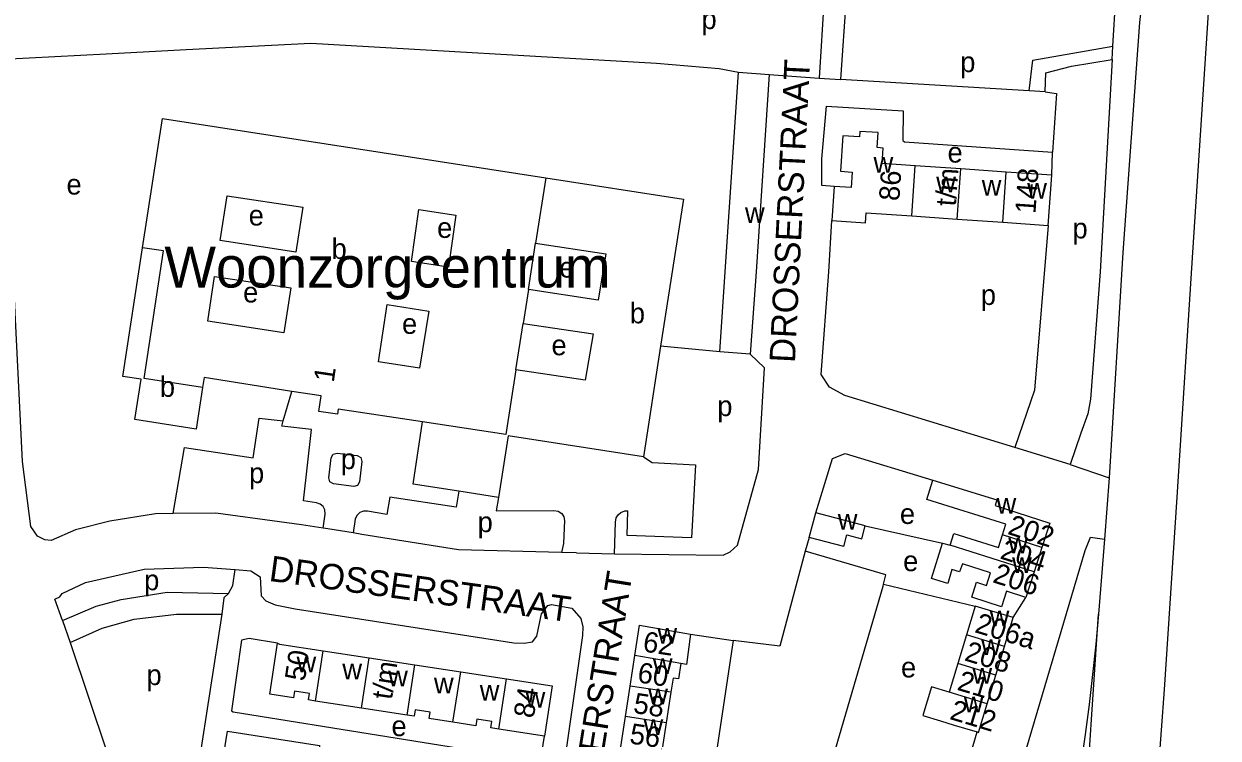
# Model space of a CAD drawing. Extents: x 159294 to 161936, y 384538 to 386517.
# Drawn here: x 161642.5 to 161876.5, y 385608.7 to 385748.5 of the extents above; entities that cross this region are included whole.
import ezdxf

# ---------------------------------------------------------------- set-up
doc = ezdxf.new("R2010")
doc.units = 0
for name, color, linetype in [('BLT_Basislijn', 7, 'Continuous'), ('BLT_Bebouwing', 7, 'Continuous'), ('BLT_Bebouwing_beschrifting', 7, 'Continuous'), ('BLT_Centroide', 7, 'Continuous'), ('BLT_Huisnummer', 7, 'Continuous'), ('BLT_Huisnummer_ tussenligend', 7, 'Continuous'), ('BLT_Huisnummer_reeks', 7, 'Continuous'), ('BLT_Onderdoorgang_en_onderverdeling', 7, 'Continuous'), ('BLT_Onderverdeling_panden', 7, 'Continuous'), ('BLT_Straatnaam', 7, 'Continuous'), ('BLT_Vlakafsluiter', 7, 'Continuous')]:
    doc.layers.add(name, color=color, linetype=linetype)

msp = doc.modelspace()

# ---------------------------------------------------------------- linework, layer by layer
at = {"layer": 'BLT_Basislijn'}
for p, q in [((161876.46, 385780.99), (161871.46, 385703.78)), ((161799.54, 385758.77), (161798.28, 385737.89)), ((161803.89, 385758.8), (161802.48, 385737.63)), ((161855.85, 385744.15), (161856.61, 385757.33)), ((161855.68, 385741.58), (161855.85, 385744.15)), ((161788.48, 385738.65), (161798.28, 385737.89)), ((161798.28, 385737.89), (161802.48, 385737.63)), ((161839.42, 385735.42), (161802.48, 385737.63)), ((161842.56, 385735.24), (161839.42, 385735.42)), ((161843.85, 385718.91), (161844.03, 385723.39)), ((161857.81, 385703.78), (161855.14, 385659.67)), ((161778.8, 385684.32), (161767.23, 385685.43)), ((161849.58, 385668.39), (161847.46, 385662.28)), ((161847.46, 385662.28), (161836.61, 385665.6)), ((161847.46, 385662.28), (161855.14, 385659.67)), ((161855.14, 385659.67), (161854.19, 385647.64)), ((161696.86, 385650.47), (161692.55, 385651.06)), ((161701.12, 385649.79), (161696.86, 385650.47)), ((161702.02, 385649.65), (161701.12, 385649.79)), ((161706.98, 385648.85), (161702.02, 385649.65)), ((161708.67, 385648.58), (161706.98, 385648.85)), ((161796.34, 385647.97), (161795.57, 385645.27)), ((161854.19, 385647.64), (161853, 385632.98)), ((161750.77, 385644.98), (161758.21, 385644.8)), ((161810.92, 385638.85), (161828.83, 385634.52)), ((161836.28, 385632.27), (161838.77, 385636.22)), ((161681.23, 385632.96), (161673.53, 385583.23)), ((161650.05, 385631.72), (161651.5, 385627.41)), ((161781.46, 385627.81), (161772.42, 385567.62)), ((161773.08, 385629.07), (161781.46, 385627.81)), ((161743.72, 385604.2), (161744.49, 385609.05)), ((161811.78, 385549.92), (161829.22, 385609.89))]:
    msp.add_line(p, q, dxfattribs=at)
for points in [[(161864.1, 385775.71), (161861.08, 385748.79), (161857.81, 385703.78)], [(161658.57, 385742.7), (161674.26, 385743.51), (161698.67, 385744.77), (161766.41, 385740.84), (161778.67, 385739.79), (161782.48, 385739.07)], [(161638.49, 385741.66), (161658.57, 385742.7)], [(161839.42, 385735.42), (161840.15, 385741.45), (161855.85, 385744.15)], [(161671.73, 385652.66), (161668.23, 385652.62), (161659.31, 385651.16), (161652.59, 385649.47), (161647.82, 385647.39), (161646.55, 385647.5), (161645.11, 385648.2), (161643.84, 385650.14), (161642.17, 385662.85), (161640.38, 385700), (161638.56, 385730.18), (161638.49, 385741.66)], [(161842.56, 385735.24), (161842.73, 385738.98), (161847.7, 385740.24), (161855.68, 385741.58)], [(161855.68, 385741.58), (161853.34, 385700), (161851.42, 385675.06), (161850.9, 385672.19), (161849.58, 385668.39)], [(161842.56, 385735.24), (161844.79, 385734.93), (161844.03, 385723.39)], [(161801.22, 385716.72), (161798.78, 385716.91), (161798.79, 385722.09), (161799.7, 385732.45), (161814.77, 385731.48), (161814.7, 385725.73), (161814.98, 385725.47), (161844.03, 385723.39)], [(161836.61, 385665.6), (161803.33, 385675.78), (161800.31, 385677.4), (161798.69, 385679.91), (161800.18, 385700), (161800.76, 385710.06)], [(161843.16, 385709.07), (161840.46, 385676.79), (161836.61, 385665.6)], [(161871.46, 385703.78), (161868.38, 385655.87), (161865.88, 385618.18), (161864.15, 385594.33)], [(161758.21, 385644.8), (161779.48, 385644.48), (161780.82, 385645.14), (161782.31, 385646.47), (161786.43, 385661.27), (161787.56, 385681.17), (161784.8, 385683.88)], [(161693.29, 385670.79), (161694.98, 385676.58)], [(161671.73, 385652.66), (161673.94, 385665.59), (161687.39, 385663.54), (161688.57, 385671.31), (161693.29, 385670.79)], [(161701.12, 385649.79), (161701.5, 385652.55), (161701.44, 385653.36), (161701.1, 385654.04), (161700.54, 385654.49), (161699.78, 385654.73), (161697.26, 385655.16), (161698.79, 385669.1), (161692.99, 385669.78), (161693.29, 385670.79)], [(161763.86, 385663.77), (161765.58, 385662.66), (161774.05, 385662.17), (161773.25, 385647.91), (161760.69, 385648.37), (161760.83, 385653.16)], [(161797.62, 385652.82), (161800.87, 385663.45), (161803.38, 385664.44), (161820.54, 385659.2)], [(161727.66, 385657.04), (161727.19, 385653.88), (161714.17, 385655.86), (161713.59, 385652.48), (161709.77, 385653.11), (161708.99, 385653.12), (161708.28, 385652.84), (161707.67, 385652.25), (161707.35, 385651.57), (161706.98, 385648.85)], [(161735.46, 385655.82), (161734.97, 385653.18), (161746.3, 385653.27), (161747.16, 385653.13), (161747.85, 385652.68), (161748.26, 385652.02), (161748.41, 385651.31), (161748.21, 385646.8), (161747.8, 385645.05)], [(161758.21, 385644.8), (161758.39, 385650.98), (161758.51, 385651.79), (161758.88, 385652.43), (161759.43, 385652.88), (161760.24, 385653.16), (161760.83, 385653.16)], [(161692.55, 385651.06), (161680.1, 385652.75), (161671.73, 385652.66)], [(161747.8, 385645.05), (161727.64, 385645.52), (161708.67, 385648.58)], [(161807.31, 385650.25), (161822.47, 385646.87)], [(161796.91, 385465.46), (161798.88, 385471.63), (161850.4, 385645.43), (161851.45, 385648.04), (161854.19, 385647.64)], [(161750.77, 385644.98), (161747.8, 385645.05)], [(161795.57, 385645.27), (161790.55, 385626.72), (161781.46, 385627.81)], [(161810.92, 385638.85), (161811.35, 385640.66), (161795.57, 385645.27)], [(161650.05, 385631.72), (161648.52, 385635.89), (161649.5, 385636.38), (161649.97, 385637.02), (161654.56, 385639.14), (161666.03, 385641.74), (161677.68, 385642.16), (161683.84, 385641.67)], [(161682.57, 385637.01), (161683.43, 385638.57), (161683.84, 385641.67)], [(161683.84, 385641.67), (161686.93, 385641.46), (161688.78, 385640.28), (161688.94, 385636.53), (161689.87, 385635.59), (161691.7, 385634.79), (161695.65, 385633.97), (161738.45, 385627.35), (161740.5, 385627.26), (161742.09, 385627.55), (161743, 385628.64), (161743.86, 385633.03), (161745.11, 385634.62), (161745.83, 385634.87), (161749.81, 385634.1), (161751.59, 385632.1), (161751.97, 385630.49), (161751.94, 385628.77), (161747.75, 385599.58)], [(161650.05, 385631.72), (161656.63, 385634.49), (161661.51, 385635.82), (161670.56, 385637.25), (161682.57, 385637.01)], [(161682.57, 385637.01), (161681.67, 385636.14), (161681.23, 385632.96)], [(161792.92, 385577.31), (161810.82, 385638.44), (161810.92, 385638.85)], [(161651.5, 385627.41), (161657.79, 385630.24), (161664.1, 385632), (161672.34, 385632.95), (161681.23, 385632.96)], [(161853, 385632.98), (161852.48, 385627.07), (161851.87, 385621.16), (161851.18, 385615.26), (161850.42, 385609.38), (161849.57, 385603.5), (161848.65, 385597.63), (161847.65, 385591.78), (161846.57, 385585.94), (161845.4, 385580.11), (161844.17, 385574.31), (161842.85, 385568.52), (161841.46, 385562.74), (161839.98, 385556.99), (161838.43, 385551.26), (161838.09, 385550.01)], [(161651.5, 385627.41), (161658.81, 385605.83), (161665.04, 385586.2), (161666.87, 385584.38), (161673.53, 385583.23)], [(161692.17, 385627.26), (161686.62, 385628.18), (161685.09, 385627.88), (161683.12, 385614.03), (161683.48, 385613.84), (161743.72, 385604.2)], [(161686.14, 385599.73), (161681.24, 385600.62), (161681.18, 385602.7), (161682.39, 385610.04), (161700.36, 385607.27), (161699.5, 385597.57), (161694.22, 385562.54), (161675.39, 385565.45), (161676.6, 385572.92), (161681.9, 385572.51)]]:
    msp.add_lwpolyline(points, dxfattribs=at)
msp.add_lwpolyline([(161703.08, 385664.28), (161703.84, 385664.45), (161707.74, 385664.05), (161708.48, 385663.65), (161708.65, 385662.84), (161708.22, 385658.86), (161707.8, 385658.18), (161707.1, 385657.97), (161703.15, 385658.47), (161702.4, 385658.88), (161702.21, 385659.64), (161702.67, 385663.58)], close=True, dxfattribs=at)
at = {"layer": 'BLT_Bebouwing'}
for p, q in [((161782.48, 385739.07), (161788.48, 385738.65)), ((161817.11, 385720.77), (161810.65, 385721.22)), ((161826.02, 385720.15), (161817.11, 385720.77)), ((161834.94, 385719.53), (161826.02, 385720.15)), ((161843.85, 385718.91), (161834.94, 385719.53)), ((161843.16, 385709.07), (161843.85, 385718.91)), ((161801.22, 385716.72), (161800.76, 385710.06)), ((161807.52, 385711.55), (161816.43, 385710.93)), ((161816.43, 385710.93), (161825.34, 385710.31)), ((161825.34, 385710.31), (161834.25, 385709.69)), ((161834.25, 385709.69), (161843.16, 385709.07)), ((161741.32, 385696.5), (161742.73, 385705.57)), ((161738.87, 385680.81), (161740.28, 385689.87)), ((161784.8, 385683.88), (161778.8, 385684.32)), ((161796.34, 385647.97), (161797.62, 385652.82)), ((161807.31, 385650.25), (161797.62, 385652.82)), ((161803.09, 385646.19), (161803.73, 385648.49)), ((161803.73, 385648.49), (161806.62, 385647.72)), ((161806.62, 385647.72), (161807.31, 385650.25)), ((161803.09, 385646.19), (161796.34, 385647.97)), ((161822.47, 385646.87), (161823.97, 385646.44)), ((161841.93, 385646.03), (161840.4, 385641.26)), ((161840.4, 385641.26), (161838.77, 385636.22)), ((161828.83, 385634.52), (161827.13, 385628.9)), ((161834.59, 385626.65), (161836.28, 385632.27)), ((161827.13, 385628.9), (161825.44, 385623.29)), ((161701.13, 385625.79), (161710.1, 385624.41)), ((161832.89, 385621.04), (161834.59, 385626.65)), ((161710.1, 385624.41), (161719.08, 385623.04)), ((161719.08, 385623.04), (161728.06, 385621.66)), ((161761.25, 385618.87), (161762.16, 385624.83)), ((161825.44, 385623.29), (161823.74, 385617.67)), ((161728.06, 385621.66), (161737.03, 385620.29)), ((161831.2, 385615.42), (161832.89, 385621.04)), ((161760.35, 385612.91), (161761.25, 385618.87)), ((161708.59, 385614.56), (161699.62, 385615.93)), ((161769.24, 385617.65), (161768.33, 385611.69)), ((161717.57, 385613.18), (161708.59, 385614.56)), ((161759.44, 385606.95), (161760.35, 385612.91)), ((161768.33, 385611.69), (161767.42, 385605.73)), ((161744.49, 385609.05), (161735.52, 385610.43))]:
    msp.add_line(p, q, dxfattribs=at)
for points in [[(161778.8, 385684.32), (161782.48, 385739.07)], [(161788.48, 385738.65), (161785.97, 385700), (161784.8, 385683.88)], [(161665.72, 385704.66), (161669.63, 385730.03), (161744.73, 385718.41)], [(161802.93, 385726.62), (161802.49, 385719.7)], [(161810.65, 385721.22), (161810.84, 385724.22), (161809.65, 385724.3), (161809.84, 385727.24), (161806.26, 385727.47), (161806.19, 385726.41), (161802.93, 385726.62)], [(161802.49, 385719.7), (161804.78, 385719.52), (161804.54, 385716.49), (161801.22, 385716.72)], [(161744.73, 385718.41), (161771.72, 385714.24), (161767.23, 385685.43)], [(161800.76, 385710.06), (161807.38, 385709.6), (161807.52, 385711.55)], [(161677.49, 385677.36), (161676.23, 385669.19), (161664.21, 385671.05), (161665.44, 385678.96), (161661.84, 385679.52), (161665.72, 385704.66)], [(161742.73, 385705.57), (161756.5, 385703.51), (161754.96, 385694.46), (161741.32, 385696.5)], [(161740.28, 385689.87), (161754, 385687.82), (161752.46, 385678.78), (161738.87, 385680.81)], [(161767.23, 385685.43), (161763.86, 385663.77)], [(161694.98, 385676.58), (161677.79, 385679.29), (161677.49, 385677.36)], [(161720.58, 385670.61), (161704.07, 385673.09), (161703.92, 385672.11), (161700.28, 385672.66), (161700.73, 385675.68), (161694.98, 385676.58)], [(161727.66, 385657.04), (161718.71, 385658.44), (161720.58, 385670.61)], [(161763.86, 385663.77), (161737.35, 385667.89), (161735.46, 385655.82)], [(161834.2, 385648.51), (161834.84, 385650.58), (161819.36, 385655.38), (161820.54, 385659.2)], [(161820.54, 385659.2), (161833.09, 385655.31), (161832.75, 385654.24)], [(161735.46, 385655.82), (161727.66, 385657.04)], [(161832.75, 385654.24), (161843.46, 385650.79), (161841.93, 385646.03)], [(161823.97, 385646.44), (161824.7, 385648.73), (161833.43, 385646.03), (161834.2, 385648.51)], [(161838.77, 385636.22), (161835, 385637.43), (161834.03, 385634.41), (161828.18, 385636.29), (161829.12, 385639.22), (161831.09, 385638.58), (161831.87, 385641.02), (161826.36, 385642.79), (161825.81, 385641.27), (161824.28, 385641.72), (161823.5, 385638.96), (161820.28, 385639.96), (161822.47, 385646.87)], [(161836.28, 385632.27), (161831.49, 385633.71), (161828.83, 385634.52)], [(161762.16, 385624.83), (161763.07, 385630.78), (161773.08, 385629.07)], [(161773.08, 385629.07), (161772.29, 385623.12), (161771.2, 385623.29)], [(161699.62, 385615.93), (161698.21, 385616.15), (161698.41, 385617.41), (161695.49, 385617.86), (161695.3, 385616.6), (161690.64, 385617.31), (161692.17, 385627.26)], [(161692.17, 385627.26), (161692.55, 385627.11), (161701.13, 385625.79)], [(161771.2, 385623.29), (161770.74, 385620.27), (161769.66, 385620.44), (161769.24, 385617.65)], [(161737.03, 385620.29), (161746, 385618.91), (161744.49, 385609.05)], [(161823.74, 385617.67), (161820.32, 385618.73), (161818.62, 385613.09), (161822.05, 385612.06), (161824.71, 385611.25), (161829.22, 385609.89)], [(161726.54, 385611.8), (161721.85, 385612.53), (161722.05, 385613.79), (161719.15, 385614.23), (161718.96, 385612.97), (161717.57, 385613.18)], [(161829.22, 385609.89), (161829.5, 385609.81), (161831.2, 385615.42)], [(161735.52, 385610.43), (161733.93, 385610.67), (161734.12, 385611.94), (161731.21, 385612.38), (161731.02, 385611.12), (161726.54, 385611.8)]]:
    msp.add_lwpolyline(points, dxfattribs=at)
for points in [[(161682.27, 385714.87), (161697.14, 385712.68), (161695.78, 385703.84), (161680.93, 385706.13)], [(161719.86, 385712.18), (161727.08, 385711.07), (161725.63, 385700.93), (161718.41, 385702.04)], [(161679.84, 385699.06), (161694.77, 385696.86), (161693.41, 385688.02), (161678.49, 385690.32)], [(161713.65, 385693.61), (161721.82, 385692.3), (161719.96, 385681.11), (161711.96, 385682.39)]]:
    msp.add_lwpolyline(points, close=True, dxfattribs=at)
at = {"layer": 'BLT_Onderdoorgang_en_onderverdeling'}
for p, q in [((161744.73, 385718.41), (161742.73, 385705.57)), ((161741.32, 385696.5), (161740.28, 385689.87))]:
    msp.add_line(p, q, dxfattribs=at)
for points in [[(161677.49, 385677.36), (161666.01, 385679.1), (161669.82, 385704.07), (161665.72, 385704.66)], [(161738.87, 385680.81), (161736.9, 385668.16), (161720.58, 385670.61)]]:
    msp.add_lwpolyline(points, dxfattribs=at)
at = {"layer": 'BLT_Onderverdeling_panden'}
for p, q in [((161816.43, 385710.93), (161817.11, 385720.77)), ((161825.34, 385710.31), (161826.02, 385720.15)), ((161834.25, 385709.69), (161834.94, 385719.53)), ((161841.93, 385646.03), (161834.2, 385648.51)), ((161840.4, 385641.26), (161823.97, 385646.44)), ((161834.59, 385626.65), (161827.13, 385628.9)), ((161699.62, 385615.93), (161701.13, 385625.79)), ((161708.59, 385614.56), (161710.1, 385624.41)), ((161717.57, 385613.18), (161719.08, 385623.04)), ((161771.2, 385623.29), (161762.16, 385624.83)), ((161832.89, 385621.04), (161825.44, 385623.29)), ((161726.54, 385611.8), (161728.06, 385621.66)), ((161735.52, 385610.43), (161737.03, 385620.29)), ((161769.24, 385617.65), (161761.25, 385618.87)), ((161831.2, 385615.42), (161823.74, 385617.67)), ((161768.33, 385611.69), (161760.35, 385612.91))]:
    msp.add_line(p, q, dxfattribs=at)
at = {"layer": 'BLT_Vlakafsluiter'}
msp.add_line((161847.89, 385556.26), (161853, 385632.98), dxfattribs=at)

# ---------------------------------------------------------------- texts
at = {"layer": 'BLT_Bebouwing_beschrifting'}
msp.add_text('Woonzorgcentrum', height=8, dxfattribs=at).set_placement((161670, 385696.91))
at = {"layer": 'BLT_Centroide'}
for s, p in [('p', (161775.24, 385747.52)), ('p', (161825.93, 385739.08)), ('e', (161823.44, 385721.38)), ('w', (161808.94, 385719.38)), ('w', (161821.22, 385715.53)), ('e', (161650.81, 385715.12)), ('w', (161830.14, 385714.92)), ('w', (161839.05, 385714.3)), ('e', (161686.51, 385709.05)), ('w', (161783.75, 385709.55)), ('e', (161723.43, 385706.63)), ('p', (161847.93, 385706.52)), ('b', (161702.76, 385702.5)), ('e', (161747.37, 385698.86)), ('e', (161685.42, 385693.99)), ('p', (161829.96, 385693.5)), ('b', (161761.19, 385689.9)), ('e', (161716.56, 385687.84)), ('e', (161745.84, 385683.65)), ('b', (161669.11, 385675.51)), ('p', (161778.33, 385671.73)), ('p', (161704.55, 385661.36)), ('p', (161686.58, 385658.61)), ('w', (161833.04, 385652.62)), ('e', (161814.11, 385650.62)), ('p', (161731.37, 385649.01)), ('w', (161801.93, 385649.5)), ('w', (161835.34, 385644.88)), ('e', (161814.74, 385641.37)), ('w', (161836.09, 385641)), ('p', (161666.03, 385637.64)), ('w', (161831.7, 385630.59)), ('w', (161766.6, 385627.19)), ('w', (161830.02, 385624.97)), ('w', (161695.89, 385621.59)), ('w', (161704.86, 385620.17)), ('w', (161765.7, 385621.25)), ('e', (161814.32, 385620.56)), ('p', (161666.49, 385619.07)), ('w', (161713.83, 385618.8)), ('w', (161722.81, 385617.42)), ('w', (161828.31, 385619.34)), ('w', (161731.78, 385616.03)), ('w', (161764.79, 385615.28)), ('w', (161740.77, 385614.67)), ('w', (161826.62, 385613.75)), ('e', (161714.49, 385609.07)), ('w', (161763.88, 385609.31))]:
    msp.add_text(s, height=4, dxfattribs=at).set_placement(p)
at = {"layer": 'BLT_Huisnummer'}
for s, rotation, p in [('1', 81.607, (161703.17, 385678.21)), ('202', 342.1558, (161835.04, 385648.7)), ('206', 342.1558, (161832.1, 385639.25)), ('206a', 343.2063, (161828.58, 385629.46)), ('62', 351.3383, (161763.59, 385625.68)), ('212', 343.1998, (161823.68, 385612.46)), ('56', 351.3383, (161760.98, 385607.67))]:
    msp.add_text(s, height=4, rotation=rotation, dxfattribs=at).set_placement(p)
at = {"layer": 'BLT_Huisnummer_ tussenligend'}
for s, rotation, p in [('204', 342.1558, (161833.55, 385643.91)), ('208', 343.1992, (161826.56, 385623.94)), ('60', 351.3383, (161762.53, 385619.62)), ('210', 343.1992, (161825.13, 385618.18)), ('58', 351.3383, (161761.73, 385613.64))]:
    msp.add_text(s, height=4, rotation=rotation, dxfattribs=at).set_placement(p)
at = {"layer": 'BLT_Huisnummer_reeks'}
for s, rotation, p in [('86', 86.0178, (161813.98, 385713.78)), ('t/m', 86.0178, (161825.07, 385712.75)), ('148', 86.0178, (161840.66, 385711.27)), ('50', 81.284, (161697.5, 385619.7)), ('t/m', 81.2831, (161714.55, 385616.08)), ('84', 81.284, (161742.35, 385612.45))]:
    msp.add_text(s, height=4, rotation=rotation, dxfattribs=at).set_placement(p)
at = {"layer": 'BLT_Straatnaam'}
for s, rotation, p in [('DROSSERSTRAAT', 87.1451, (161793.54, 385682.1)), ('DROSSERSTRAAT', 352.1681, (161690.33, 385639.49)), ('VLASSERSTRAAT', 80.897, (161752.66, 385584.35))]:
    msp.add_text(s, height=5, rotation=rotation, dxfattribs=at).set_placement(p)

doc.saveas('drawing.dxf')
